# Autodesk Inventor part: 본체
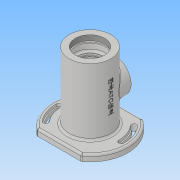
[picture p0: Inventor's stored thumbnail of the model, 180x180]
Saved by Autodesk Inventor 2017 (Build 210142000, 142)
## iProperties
Part Number: 본체
Material: 일반
Document SubType Name: Modeling
Designer: user
Density: 1 g/cm^3
Appearance: 기본값
Author: user
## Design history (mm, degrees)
sketch "스케치1"
  geometry: L1 (-33.985, 47)-(33.985, 47); L2 (33.985, 47)-(33.985, -47); L3 (33.985, -47)-(-33.985, -47); L4 (-33.985, -47)-(-33.985, 47); L5 (-33.985, 47)-(33.985, -47); L6 (33.985, 47)-(-33.985, -47); L7 (0, 0)-(0, 47); L8 (0, 0)-(48, 0); L9 (0, 0)-(36.77, 30.854); L10 (-58, 0)-(58, 0); L11 (0, 0)-(-36.77, -30.854); L12 (0, 0)-(-48, 0); A1 r 58 centre (0, 0) between (33.985, -47) and (33.985, 47); A2 r 58 centre (0, 0) between (-33.985, 47) and (-33.985, -47); A3 r 48 centre (0, 0) between (36.77, 30.854) and (-48, 0); A4 r 48 centre (0, 0) between (48, 0) and (36.77, 30.854); A5 r 52 centre (0, 0) between (52, 0) and (39.834, 33.425); A6 r 44 centre (0, 0) between (44, 0) and (33.706, 28.283); A7 r 4 centre (48, 0) between (44, 0) and (52, 0); A8 r 4 centre (36.77, 30.854) between (39.834, 33.425) and (33.706, 28.283); A9 r 48 centre (0, 0) between (-48, 0) and (-36.77, -30.854); A10 r 52 centre (0, 0) between (-52, 0) and (-39.834, -33.425); A11 r 44 centre (0, 0) between (-44, 0) and (-33.706, -28.283); A12 r 4 centre (-48, 0) between (-44, 0) and (-52, 0); A13 r 4 centre (-36.77, -30.854) between (-39.834, -33.425) and (-33.706, -28.283); 4 further points
  constraints: 29 point on circle, 24 end point, 13 centre point, 8 tangent, 6 midpoint, 4 coincident, 4 horizontal alignment, 2 parallel, 1 horizontal, 1 perpendicular, 1 point on line
  dimensions: "d5" = 94 distance of L1.end L2.end; "d6" = 58 radius of A1; "d7" = 58 radius of A2; "d8" = 96 diameter of A3; "d9" = 40 deg angle of L8 L9; "d10" = 8 diameter of A7; "d11" = 40 deg angle of L12 L11; "d12" = 8 diameter of A13
extrude "돌출1" new body sketch "스케치1" distance "d13" = 13; taper "d14" = 0 deg
sketch "스케치2"
  geometry: C1 r 32 at (0, 0); A1 r 52 centre (0, 0) between (52, 0) and (39.834, 33.425) reference
  constraints: 1 centre point, 1 coincident
  dimensions: "d15" = 64 diameter of C1
extrude "돌출2" join sketch "스케치2" distance "d16" = 102; taper "d17" = 0 deg
sketch "스케치3"
  geometry: L1 (32, 115)-(-32, 115) reference; L2 (0, 0)-(0, 115); L3 (0, 115)-(-22.5, 115); L4 (-22.5, 115)-(-22.5, 107); L5 (-22.5, 107)-(-24, 107); L6 (-24, 107)-(-24, 104); L7 (-24, 104)-(-22.5, 104); L8 (-22.5, 104)-(-22.5, 93); L9 (-22.5, 93)-(-17.5, 93); L10 (-17.5, 93)-(-17.5, 90.75); L11 (-17.5, 90.75)-(-18.5, 90.75); L12 (-18.5, 90.75)-(-18.5, 89); L13 (-18.5, 89)-(-17.5, 89); L14 (-17.5, 89)-(-17.5, 78); L15 (-17.5, 78)-(-27, 78); L16 (-27, 78)-(-27, 40); L17 (-27, 40)-(-17.5, 40); L18 (-17.5, 40)-(-17.5, 29); L19 (-17.5, 29)-(-15, 29); L20 (-15, 29)-(-15, 24); L21 (-15, 24)-(-11, 24); L22 (33.985, 0)-(-33.985, 0) reference; L23 (-20, 14)-(-30, 0); L24 (-11, 24)-(-11, 21.3); L25 (-11, 21.3)-(-15, 21.3); L26 (-15, 21.3)-(-15, 14.7); L27 (-15, 14.7)-(-15.404, 14); L28 (-15.404, 14)-(-20, 14)
  constraints: 52 end point, 17 perpendicular, 4 point on line, 2 horizontal, 2 vertical, 1 midpoint
  dimensions: "d18" = 45 diameter of L4 L2; "d19" = 48 diameter of L6 L2; "d20" = 45 diameter of L8 L2; "d21" = 35 diameter of L10 L2; "d22" = 37 diameter of L12 L2; "d23" = 35 diameter of L14 L2; "d24" = 54 diameter of L16 L2; "d25" = 30 diameter of L20 L2; "d28" = 40 diameter of L23.start L2; "d29" = 60 diameter of L23.end L2; "d30" = 5 distance of L19.end L20.end; "d31" = 29 distance between parallel lines of L22 L19; "d32" = 14 distance from line of L22 L23.start; "d33" = 11 distance of L17.end L18.end; "d34" = 11 distance of L13.end L14.end; "d35" = 3 distance of L5.end L6.end; "d36" = 8 distance of L3.end L4.end; "d37" = 22 distance between parallel lines of L1 L9; "d38" = 1.75 distance of L11.end L12.end; "d39" = 4 distance from line of L13.end L9; "d44" = 22 diameter of L24 L2; "d45" = 30 diameter of L26 L2; "d46" = 30 deg angle of L27 L26; "d47" = 0.7 distance from line of L28 L26.end; "d48" = 7.3 distance between parallel lines of L28 L25
revolve "회전1" sketch "스케치3" stored, may be unused: angle "d49" = 360 deg
sketch "스케치4"
  geometry: L1 (33.985, 47)-(-33.985, 47) reference; L2 (-33.985, -47)-(33.985, -47) reference; C1 r 36 at (0, 0); C2 r 30 at (0, 0) reference; A1 r 44 centre (0, 0) between (-33.706, 28.283) and (-44, 0) reference; A2 r 4 centre (48, 0) between (52, 0) and (44, 0) reference; A3 r 52 centre (0, 0) between (39.834, -33.425) and (52, 0) reference; A4 r 4 centre (36.77, -30.854) between (33.706, -28.283) and (39.834, -33.425) reference; A5 r 44 centre (0, 0) between (33.706, -28.283) and (44, 0) reference; A6 r 4 centre (-48, 0) between (-52, 0) and (-44, 0) reference; A7 r 52 centre (0, 0) between (-39.834, 33.425) and (-52, 0) reference; A8 r 4 centre (-36.77, 30.854) between (-33.706, 28.283) and (-39.834, 33.425) reference; A9 r 44 centre (0, 0) between (-33.706, 28.283) and (-44, 0) reference; A10 r 58 centre (0, 0) between (-33.985, 47) and (-33.985, -47) reference; A11 r 58 centre (0, 0) between (33.985, -47) and (33.985, 47) reference
  constraints: 1 centre point, 1 coincident
  dimensions: "d50" = 72 diameter of C1
extrude "돌출3" cut sketch "스케치4" distance "d51" = 3; taper "d52" = 0 deg
sketch "스케치5"
  geometry: A1 r 44 centre (0, 0) between (-33.706, 28.283) and (-44, 0) reference; A2 r 4 centre (-48, 0) between (-52, 0) and (-44, 0) reference; A3 r 52 centre (0, 0) between (-39.834, 33.425) and (-52, 0) reference; A4 r 4 centre (-36.77, 30.854) between (-33.706, 28.283) and (-39.834, 33.425) reference; A5 r 44 centre (0, 0) between (33.706, -28.283) and (44, 0) reference; A6 r 4 centre (48, 0) between (52, 0) and (44, 0) reference; A7 r 52 centre (0, 0) between (39.834, -33.425) and (52, 0) reference; A8 r 4 centre (36.77, -30.854) between (33.706, -28.283) and (39.834, -33.425) reference; A9 r 45.75 centre (0, 0) between (35.047, -29.408) and (45.75, 0); A10 r 2.25 centre (36.77, -30.854) between (35.047, -29.408) and (38.494, -32.3); A11 r 50.25 centre (0, 0) between (38.494, -32.3) and (50.25, 0); A12 r 2.25 centre (48, 0) between (50.25, 0) and (45.75, 0); A13 r 2.25 centre (-48, 0) between (-50.25, 0) and (-45.75, 0); A14 r 45.75 centre (0, 0) between (-35.047, 29.408) and (-45.75, 0); A15 r 2.25 centre (-36.77, 30.854) between (-35.047, 29.408) and (-38.494, 32.3); A16 r 50.25 centre (0, 0) between (-38.494, 32.3) and (-50.25, 0)
  constraints: 16 point on circle, 8 centre point, 6 other
  dimensions: "d53" = 1.75 radial gap between concentric circles of A5 A9; "d54" = 1.75 radial gap between concentric circles of A3 A16
extrude "돌출4" join sketch "스케치5" distance "d55" = 5.6; taper "d56" = 0 deg
sketch "스케치6"
  geometry: C1 r 4 at (36.77, 30.854); C2 r 4 at (-36.77, -30.854); A1 r 4 centre (-36.77, -30.854) between (-39.834, -33.425) and (-33.706, -28.283) reference; A2 r 4 centre (36.77, 30.854) between (39.834, 33.425) and (33.706, 28.283) reference
  constraints: 2 centre point, 2 coincident
  dimensions: "d57" = 8 diameter of C1; "d58" = 8 diameter of C2
extrude "돌출5" cut sketch "스케치6" stored distance "d59" = 5.6; taper "d60" = 0 deg
node "작업 평면1"
sketch "스케치7"
  geometry: L1 (32, 115)-(-32, 115) reference; C1 r 25 at (0, 59); 1 further point
  constraints: 1 centre point, 1 vertical alignment
  dimensions: "d62" = 50 diameter of C1; "d63" = 56 distance from line of L1 C1.centre
extrude "돌출6" join sketch "스케치7" stored distance "d64" = 5.6; taper "d65" = 5 deg
hole "구멍1" diameter "d68" = 32; stored, may be unused: countersink angle "d72" = 90 deg, drill point angle "d74" = 0 deg; dims "d66" = 10, "d67" = 10, "d69" = 6, "d70" = 4, "d71" = 2, "d73" = 8
sketch "스케치8"
  geometry: L1 (0, 0)-(-20.5, 0); L2 (0, 0)-(20.5, 0); C1 r 25 at (0, 0) reference; A1 r 20.5 centre (0, 0) between (-20.5, 0) and (20.5, 0); 3 further points
  constraints: 4 end point, 3 coincident, 2 point on circle, 1 centre point
  dimensions: "d75" = 41 diameter of A1
hole "구멍2" sketch "스케치8" at (-20.5, 0), (20.5, 0) diameter "d76" = 2.621; stored, may be unused: countersink angle "d80" = 90 deg, drill point angle "d82" = 118 deg; dims "d77" = 6, "d78" = 4, "d79" = 2, "d81" = 8
node "작업 평면2"
sketch "스케치9"
  geometry: L1 (3.602, 76.887)-(3.602, 27.113); L2 (3.602, 27.113)-(-3.602, 27.113); L3 (-3.602, 27.113)-(-3.602, 76.887); L4 (-3.602, 76.887)-(3.602, 76.887); L5 (3.602, 76.887)-(-3.602, 27.113); L6 (47, -10)-(-47, -10) reference; 2 further points
  constraints: 2 end point, 1 midpoint, 1 vertical alignment, 2 other
  dimensions: "d83" = 62 distance from line of point (0, 52) L6
feature "엠보싱1" sketch "스케치9" dims "d5" = 94, "d6" = 58, "d7" = 58, "d8" = 96, "d9" = 40 deg, "d10" = 8, "d11" = 40 deg, "d12" = 8, "d84" = 0.5, "d85" = 0
chamfer "모따기1" distance "d86" = 1; stored, may be unused: second distance "d87" = 2, angle "d88" = 45 deg
chamfer "모따기2" distance "d89" = 1; stored, may be unused: second distance "d90" = 2, angle "d91" = 45 deg
feature "스레드1" dims "d92" = 10, "d93" = 0
fillet "모깎기1" dims "d94" = 0.6
fillet "모깎기2" dims "d95" = 0.5
fillet "모깎기3" dims "d96" = 3
chamfer "모따기3" distance "d97" = 1; stored, may be unused: second distance "d98" = 2, angle "d99" = 45 deg
chamfer "모따기4" distance "d100" = 1; stored, may be unused: second distance "d101" = 2, angle "d102" = 45 deg
fillet "모깎기4" dims "d103" = 3
fillet "모깎기6" dims "d105" = 3
fillet "모깎기7" dims "d106" = 3
fillet "모깎기8" dims "d107" = 3
node "솔리드1"
node "투영된 루프1"
other parameters: "d61" = 38
